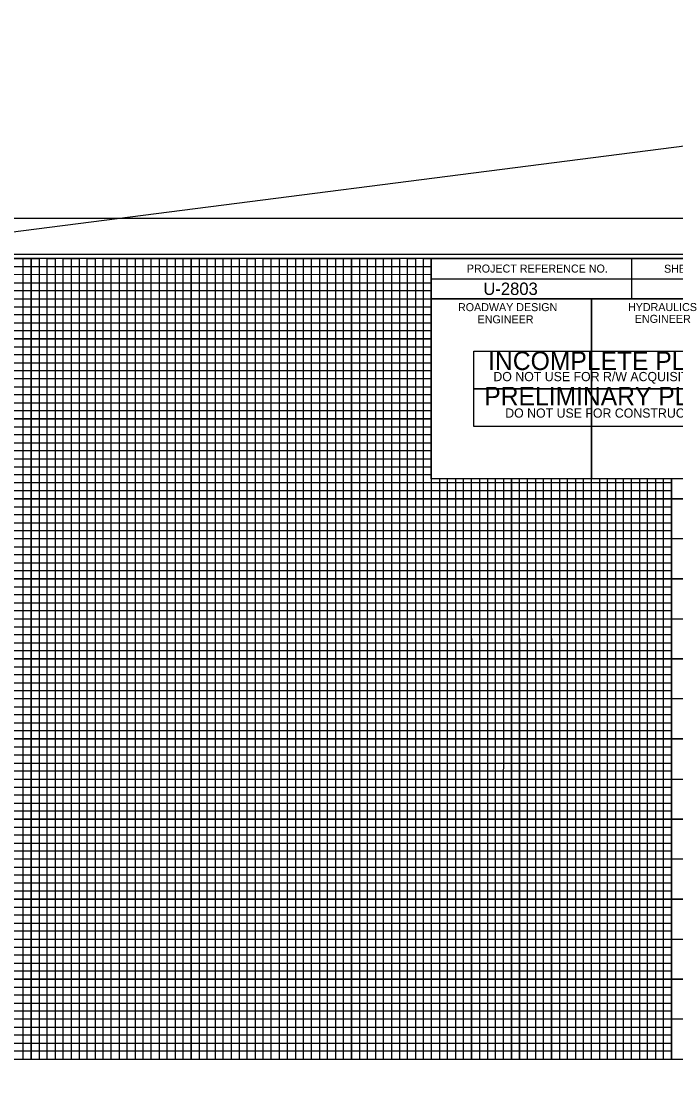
# Model space of a CAD drawing. Extents: x 571503 to 593215, y -77195 to -51828.
# Drawn here: x 586970 to 587378, y -53168 to -52498 of the extents above; entities that cross this region are included whole.
import ezdxf

# ---------------------------------------------------------------- set-up
doc = ezdxf.new("R2010")
doc.units = 0
for name, color, linetype in [('Prop PFL Text', 7, 'Continuous'), ('Sheet Clip Boundary CELL', 7, 'Continuous'), ('Sheet Data Field CELL', 7, 'Continuous'), ('Sheet DOT Grid CELL', 7, 'Continuous'), ('Sheet Plot Border Inside CELL', 7, 'Continuous'), ('Sheet Plot Border Outside CELL', 7, 'Continuous'), ('Sheet Profile CELL', 7, 'Continuous'), ('Sheet Profile Grid Major CELL', 7, 'Continuous'), ('Sheet Profile Grid Middle CELL', 7, 'Continuous'), ('Sheet Profile Grid Minor CELL', 7, 'Continuous'), ('Sheet Sticker Incomplete CELL', 7, 'Continuous'), ('Sheet Sticker Preliminary CELL', 7, 'Continuous')]:
    doc.layers.add(name, color=color, linetype=linetype)

msp = doc.modelspace()

# ---------------------------------------------------------------- linework, layer by layer
at = {"layer": 'Prop PFL Text'}
msp.add_line((571799.62, -54572.45), (593215.36, -51828.37), dxfattribs=at)
at = {"layer": 'Sheet Clip Boundary CELL'}
msp.add_lwpolyline([(585975.93, -52646.12), (585975.93, -53146.12), (587375.93, -53146.12), (587375.93, -52783.67), (587225.88, -52783.67), (587225.88, -52646.12)], close=True, dxfattribs=at)
at = {"layer": 'Sheet DOT Grid CELL'}
for p, q in [((586975.93, -53146.12), (586975.93, -52646.12)), ((586975.93, -53146.12), (586975.93, -52646.12)), ((587025.93, -53146.12), (587025.93, -52646.12)), ((587025.93, -53146.12), (587025.93, -52646.12)), ((587075.93, -53146.12), (587075.93, -52646.12)), ((587075.93, -53146.12), (587075.93, -52646.12)), ((587125.93, -53146.12), (587125.93, -52646.12)), ((587125.93, -53146.12), (587125.93, -52646.12)), ((587175.93, -53146.12), (587175.93, -52646.12)), ((587175.93, -53146.12), (587175.93, -52646.12)), ((587225.88, -52696.12), (585925.93, -52696.12)), ((585925.93, -52746.12), (587225.88, -52746.12)), ((587225.88, -52746.12), (585925.93, -52746.12)), ((587225.93, -53146.12), (587225.93, -52783.67)), ((587225.93, -53146.12), (587225.93, -52783.67)), ((587275.93, -53146.12), (587275.93, -52783.67)), ((587275.93, -53146.12), (587275.93, -52783.67)), ((587325.93, -53146.12), (587325.93, -52783.67)), ((587325.93, -53146.12), (587325.93, -52783.67)), ((587375.93, -53146.12), (587375.93, -52783.67)), ((587375.93, -53146.12), (587375.93, -52783.67)), ((585925.93, -52796.12), (587425.93, -52796.12)), ((587425.93, -52796.12), (585925.93, -52796.12)), ((585925.93, -52846.12), (587425.93, -52846.12)), ((587425.93, -52846.12), (586575.93, -52846.12)), ((587425.93, -52896.12), (585925.93, -52896.12)), ((586575.93, -52896.12), (587425.93, -52896.12)), ((585925.93, -52946.12), (587425.93, -52946.12)), ((587425.93, -52946.12), (585925.93, -52946.12)), ((585925.93, -52996.12), (587425.93, -52996.12)), ((587425.93, -52996.12), (585925.93, -52996.12)), ((585925.93, -53046.12), (587425.93, -53046.12)), ((587425.93, -53046.12), (585925.93, -53046.12)), ((585925.93, -53096.12), (587425.93, -53096.12)), ((587425.93, -53096.12), (585925.93, -53096.12))]:
    msp.add_line(p, q, dxfattribs=at)
at = {"layer": 'Sheet Plot Border Inside CELL'}
msp.add_lwpolyline([(585771.93, -53698.67), (587438.43, -53698.67), (587438.43, -52643.57), (585771.93, -52643.57)], close=True, dxfattribs=at)
at = {"layer": 'Sheet Plot Border Outside CELL'}
msp.add_lwpolyline([(585758.93, -53721.12), (587442.93, -53721.12), (587442.93, -52621.12), (585758.93, -52621.12)], close=True, dxfattribs=at)
at = {"layer": 'Sheet Profile CELL'}
for p, q in [((587442.93, -52621.12), (585758.93, -52621.12)), ((587350.93, -52646.17), (587350.93, -52671.17)), ((587225.88, -52658.67), (587425.93, -52658.67)), ((587325.93, -52671.17), (587325.93, -52783.62)), ((585925.93, -53146.12), (587425.93, -53146.12))]:
    msp.add_line(p, q, dxfattribs=at)
for points in [[(587425.93, -52646.12), (585925.93, -52646.12), (585925.93, -53696.12), (587425.93, -53696.12)], [(587225.88, -52646.12), (587425.93, -52646.12), (587425.93, -52671.17), (587225.88, -52671.17)], [(587225.88, -52671.17), (587325.93, -52671.17), (587325.93, -52783.67), (587225.88, -52783.67)], [(587325.93, -52671.17), (587425.93, -52671.17), (587425.93, -52783.67), (587325.93, -52783.67)]]:
    msp.add_lwpolyline(points, close=True, dxfattribs=at)
at = {"layer": 'Sheet Profile Grid Major CELL'}
for points in [[(586925.93, -52646.12), (586975.93, -52646.12), (586975.93, -53146.12), (587025.93, -53146.12), (587025.93, -52646.12), (587075.93, -52646.12), (587075.93, -53146.12), (587125.93, -53146.12), (587125.93, -52646.12), (587175.93, -52646.12), (587175.93, -53146.12), (587225.93, -53146.12), (587225.93, -52646.12), (587252.23, -52646.12)], [(585925.93, -52696.12), (587225.93, -52696.12)], [(587225.93, -52746.12), (585925.93, -52746.12), (585925.93, -52796.12), (587425.93, -52796.12)], [(587275.93, -52783.67), (587275.93, -53146.12), (587325.93, -53146.12), (587325.93, -53146.12), (587325.93, -52783.67)], [(587375.93, -52783.67), (587375.93, -53146.12), (587425.93, -53146.12), (587425.93, -52796.12)], [(587425.93, -52846.12), (585925.93, -52846.12), (585925.93, -52896.12), (587425.93, -52896.12)], [(587425.93, -52946.12), (585925.93, -52946.12), (585925.93, -52996.12), (587425.93, -52996.12)], [(587425.93, -53046.12), (585925.93, -53046.12), (585925.93, -53046.12), (585925.93, -53096.12), (587425.93, -53096.12)]]:
    msp.add_lwpolyline(points, dxfattribs=at)
at = {"layer": 'Sheet Profile Grid Middle CELL'}
for p, q in [((587000.93, -52646.12), (587000.93, -53146.12)), ((587050.93, -53146.12), (587050.93, -52646.12)), ((587050.93, -52646.12), (587100.93, -52646.12)), ((587100.93, -52646.12), (587100.93, -53146.12)), ((587150.93, -53146.12), (587150.93, -52646.12)), ((587150.93, -52646.12), (587200.93, -52646.12)), ((587200.93, -52646.12), (587200.93, -53146.12)), ((585925.93, -52671.12), (587225.88, -52671.12)), ((587250.93, -53146.12), (587250.93, -52783.67)), ((587000.93, -53146.12), (587050.93, -53146.12)), ((587100.93, -53146.12), (587150.93, -53146.12)), ((587200.93, -53146.12), (587250.93, -53146.12))]:
    msp.add_line(p, q, dxfattribs=at)
for points in [[(587225.93, -52721.12), (585925.93, -52721.12), (585925.93, -52771.12), (587225.93, -52771.12)], [(587250.93, -52883.32), (587250.93, -53146.12), (587300.93, -53146.12), (587300.93, -52783.67)], [(587300.93, -52883.32), (587300.93, -53146.12), (587350.93, -53146.12), (587350.93, -52783.67)], [(587425.93, -52821.12), (585925.93, -52821.12), (585925.93, -52871.12), (587250.93, -52871.12)], [(587250.93, -52871.12), (587425.93, -52871.12)], [(587425.93, -52921.12), (585925.93, -52921.12), (585925.93, -52971.12), (587425.93, -52971.12)], [(587425.93, -53021.12), (585925.93, -53021.12), (585925.93, -53071.12), (587425.93, -53071.12)], [(587425.93, -53121.12), (585925.93, -53121.12)]]:
    msp.add_lwpolyline(points, dxfattribs=at)
at = {"layer": 'Sheet Profile Grid Minor CELL'}
for p, q in [((586575.93, -52651.12), (587225.93, -52651.12)), ((587225.93, -52656.12), (586575.93, -52656.31)), ((586575.93, -52661.12), (587225.93, -52661.12)), ((587225.88, -52781.12), (586575.93, -52781.12)), ((587375.93, -52786.12), (586575.93, -52786.12)), ((587375.93, -52791.12), (586575.93, -52791.12)), ((586575.93, -52801.12), (587375.93, -52801.12)), ((587375.93, -52806.12), (586575.93, -52806.12)), ((586575.93, -52811.12), (587375.93, -52811.12)), ((587375.93, -52831.12), (586575.93, -52831.12)), ((586575.93, -52836.12), (587375.93, -52836.12)), ((587375.93, -52856.12), (586575.93, -52856.12)), ((586575.93, -52861.12), (587375.93, -52861.12)), ((587375.93, -52881.12), (586575.93, -52881.12)), ((586575.93, -52886.12), (587375.93, -52886.12)), ((587375.93, -52891.12), (586575.93, -52891.12)), ((586575.93, -52901.12), (587375.93, -52901.12)), ((587375.93, -52906.12), (586575.93, -52906.12)), ((586575.93, -52911.12), (587375.93, -52911.12)), ((587375.93, -52916.12), (586575.93, -52916.12)), ((586575.93, -52926.12), (587375.93, -52926.12)), ((587375.93, -52931.12), (586575.93, -52931.12)), ((586575.93, -52936.12), (587375.93, -52936.12)), ((587375.93, -52941.12), (586575.93, -52941.12)), ((586575.93, -52951.12), (587375.93, -52951.12)), ((587375.93, -52956.12), (586575.93, -52956.12)), ((586575.93, -52961.12), (587375.93, -52961.12)), ((587375.93, -52966.12), (586575.93, -52966.12)), ((586575.93, -52976.12), (587375.93, -52976.12)), ((587375.93, -52981.12), (586575.93, -52981.12)), ((586575.93, -52986.12), (587375.93, -52986.12)), ((587375.93, -52991.12), (586575.93, -52991.12)), ((586575.93, -53001.12), (587375.93, -53001.12)), ((587375.93, -53006.12), (586575.93, -53006.12)), ((586575.93, -53011.12), (587375.93, -53011.12)), ((587375.93, -53016.12), (586575.93, -53016.12)), ((586575.93, -53026.12), (587375.93, -53026.12)), ((587375.93, -53031.12), (586575.93, -53031.12)), ((587375.93, -53036.12), (586575.93, -53036.12)), ((587375.93, -53041.12), (586575.93, -53041.12)), ((586575.93, -53051.12), (587375.93, -53051.12)), ((587375.93, -53056.12), (586575.93, -53056.12)), ((586575.93, -53061.12), (587375.93, -53061.12)), ((587375.93, -53066.12), (586575.93, -53066.12)), ((586575.93, -53076.12), (587375.93, -53076.12)), ((587375.93, -53081.12), (586575.93, -53081.12)), ((586575.93, -53086.12), (587375.93, -53086.12)), ((587375.93, -53091.12), (586575.93, -53091.12)), ((586575.93, -53101.12), (587375.93, -53101.12)), ((587375.93, -53106.12), (586575.93, -53106.12)), ((586575.93, -53111.12), (587375.93, -53111.12)), ((587375.93, -53116.12), (586575.93, -53116.12)), ((586575.93, -53126.12), (587375.93, -53126.12)), ((587375.93, -53131.12), (586575.93, -53131.12)), ((586575.93, -53136.12), (587375.93, -53136.12))]:
    msp.add_line(p, q, dxfattribs=at)
for points in [[(586965.93, -53146.12), (586970.93, -53146.12), (586970.93, -52646.12), (586980.93, -52646.12), (586980.93, -53146.12), (586985.93, -53146.12), (586985.93, -52646.12), (586990.93, -52646.12), (586990.93, -53146.12), (586995.93, -53146.12), (586995.93, -52646.12), (587005.93, -52646.12), (587005.93, -53146.12), (587010.93, -53146.12), (587010.93, -52646.12), (587015.93, -52646.12), (587015.93, -53146.12), (587020.93, -53146.12), (587020.93, -52646.12), (587030.93, -52646.12), (587030.93, -53146.12), (587035.93, -53146.12), (587035.93, -52646.12), (587040.93, -52646.12), (587040.93, -53146.12), (587045.93, -53146.12), (587045.93, -52646.12), (587055.93, -52646.12), (587055.93, -53146.12), (587060.93, -53146.12), (587060.93, -52646.12), (587065.93, -52646.12), (587065.93, -53146.12), (587070.93, -53146.12), (587070.93, -52646.12), (587080.93, -52646.12), (587080.93, -53146.12), (587085.93, -53146.12), (587085.93, -52646.12), (587090.93, -52646.12), (587090.93, -53146.12), (587095.93, -53146.12), (587095.93, -52646.12), (587105.93, -52646.12), (587105.93, -53146.12), (587110.93, -53146.12), (587110.93, -52646.12), (587115.93, -52646.12), (587115.93, -53146.12)], [(587115.93, -53146.12), (587120.93, -53146.12), (587120.93, -52646.12), (587130.93, -52646.12), (587130.93, -53146.12), (587135.93, -53146.12), (587135.93, -52646.12), (587140.93, -52646.12), (587140.93, -53146.12), (587145.93, -53146.12), (587145.93, -52646.12), (587155.93, -52646.12), (587155.93, -53146.12), (587160.93, -53146.12), (587160.93, -52646.12), (587165.93, -52646.12), (587165.93, -53146.12), (587170.93, -53146.12), (587170.93, -52646.12), (587180.93, -52646.12), (587180.93, -53146.12), (587185.93, -53146.12), (587185.93, -52646.12), (587190.93, -52646.12), (587190.93, -53146.12), (587195.93, -53146.12), (587195.93, -52646.12), (587205.93, -52646.12), (587205.93, -53146.12), (587210.93, -53146.12), (587210.93, -52646.12), (587215.93, -52646.12), (587215.93, -53146.12), (587220.93, -53146.12), (587220.93, -52646.12), (587230.93, -52646.12)], [(587225.93, -52666.12), (586575.93, -52666.12)], [(586575.93, -52676.12), (587225.93, -52676.12)], [(587225.88, -52681.12), (586575.93, -52681.12)], [(586575.93, -52686.12), (587225.93, -52686.12)], [(587225.93, -52691.12), (586575.93, -52691.12)], [(586575.93, -52701.12), (587225.93, -52701.12)], [(587225.93, -52706.12), (586575.93, -52706.12)], [(586575.93, -52711.12), (587225.93, -52711.12)], [(587225.93, -52716.12), (586575.93, -52716.12)], [(586575.93, -52726.12), (587225.93, -52726.12)], [(587225.93, -52731.12), (586575.93, -52731.12)], [(586575.93, -52736.12), (587225.93, -52736.12)], [(587225.93, -52741.12), (586575.93, -52741.12)], [(586575.93, -52751.12), (587225.93, -52751.12)], [(587225.93, -52756.22), (586575.93, -52756.22)], [(586575.93, -52761.12), (587225.93, -52761.12)], [(587225.93, -52766.12), (586575.93, -52766.12)], [(586575.93, -52776.12), (587225.93, -52776.12)], [(587230.93, -52783.67), (587230.93, -53146.12), (587235.93, -53146.12), (587235.93, -52783.67)], [(587240.93, -52783.67), (587240.93, -53146.12), (587245.93, -53146.12), (587245.93, -52783.67)], [(587255.93, -52783.67), (587255.93, -53146.12), (587255.93, -53146.12), (587260.93, -53146.12), (587265.93, -53146.12), (587265.93, -52783.67)], [(587260.93, -52783.67), (587260.93, -53146.12)], [(587270.93, -52783.67), (587270.83, -53146.07), (587275.83, -53146.07), (587280.93, -53146.12), (587280.93, -52783.67)], [(587280.93, -52883.32), (587280.93, -53146.12), (587285.93, -53146.12), (587285.93, -52783.67)], [(587290.93, -52783.67), (587290.93, -53146.12), (587295.93, -53146.12), (587295.93, -52783.67)], [(587305.93, -52783.67), (587305.93, -53146.12), (587310.93, -53146.12), (587310.93, -52783.67)], [(587315.93, -52783.67), (587315.93, -53146.12), (587320.93, -53146.12), (587320.93, -52783.67)], [(587330.93, -52783.67), (587330.93, -53146.12), (587335.93, -53146.12), (587335.93, -52783.67)], [(587340.93, -52783.67), (587340.93, -53146.12), (587345.93, -53146.12), (587345.93, -52783.67)], [(587355.93, -52783.67), (587355.93, -53146.12), (587360.93, -53146.12), (587360.93, -52783.67)], [(587365.93, -52783.67), (587365.93, -53146.12), (587370.93, -53146.12), (587370.93, -52783.67)], [(587375.93, -52816.12), (586575.93, -52816.12)], [(586575.93, -52826.12), (587375.93, -52826.12)], [(587375.93, -52841.12), (586575.93, -52841.12)], [(586575.93, -52851.12), (587375.93, -52851.12)], [(587375.93, -52866.12), (586575.93, -52866.12)], [(586575.93, -52876.12), (587375.93, -52876.12)], [(587375.93, -53141.12), (586575.93, -53141.12)]]:
    msp.add_lwpolyline(points, dxfattribs=at)
at = {"layer": 'Sheet Sticker Incomplete CELL'}
msp.add_lwpolyline([(587252.43, -52727.4), (587252.43, -52703.9), (587399.43, -52703.9), (587399.43, -52727.4)], close=True, dxfattribs=at)
at = {"layer": 'Sheet Sticker Preliminary CELL'}
msp.add_lwpolyline([(587252.43, -52750.9), (587252.43, -52727.4), (587399.43, -52727.4), (587399.43, -52750.9)], close=True, dxfattribs=at)

# ---------------------------------------------------------------- texts
at = {"layer": 'Sheet Data Field CELL'}
msp.add_text('U-2803   ', height=7.75, dxfattribs=at).set_placement((587258.38, -52668.81))
at = {"layer": 'Sheet Profile CELL'}
for s, height, p in [('PROJECT REFERENCE NO.', 5.0001, (587248.09, -52654.81)), ('SHEET NO.', 5, (587371.24, -52654.91)), ('ROADWAY DESIGN', 5.0001, (587242.54, -52678.91)), ('HYDRAULICS', 5, (587348.74, -52678.86)), ('ENGINEER', 5, (587254.79, -52686.51)), ('ENGINEER', 5, (587352.99, -52686.21))]:
    msp.add_text(s, height=height, dxfattribs=at).set_placement(p)
at = {"layer": 'Sheet Sticker Incomplete CELL'}
for s, height, p in [('INCOMPLETE PLANS', 11.52, (587261.39, -52715.69)), ('DO NOT USE FOR R/W ACQUISITION', 5.76, (587264.64, -52722.64))]:
    msp.add_text(s, height=height, dxfattribs=at).set_placement(p)
at = {"layer": 'Sheet Sticker Preliminary CELL'}
for s, height, p in [('PRELIMINARY PLANS', 11.52, (587258.94, -52737.74)), ('DO NOT USE FOR CONSTRUCTION', 5.76, (587272.04, -52745.44))]:
    msp.add_text(s, height=height, dxfattribs=at).set_placement(p)

doc.saveas('drawing.dxf')
